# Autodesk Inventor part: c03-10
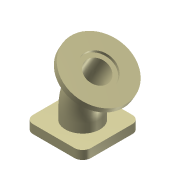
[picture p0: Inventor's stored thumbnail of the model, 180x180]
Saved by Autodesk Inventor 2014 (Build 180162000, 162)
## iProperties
Created: 2011-11
Part Number: c03-10
Material: Iron, Cast
Document SubType Name: Modeling
Designer: Thom Tremblay
Density: 7.25 g/cm^3
Mass: 1087.5 g
Surface Area: 260 cm^2
Volume: 150 cm^3
Appearance: Nylon 6
Author: Thom Tremblay
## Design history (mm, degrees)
sketch "Sketch1"
  geometry: L1 (50, -50)-(-50, -50); L2 (-50, -50)-(-50, 50); L3 (-50, 50)-(50, 50); L4 (50, 50)-(50, -50); C1 r 20 at (0, 0); C2 r 30 at (0, 0); 3 further points
  constraints: 8 end point, 2 centre point, 2 coincident, 2 midpoint, 2 parallel, 2 perpendicular, 1 horizontal, 1 horizontal alignment, 1 vertical alignment
  dimensions: "d0" = 100 distance of L2.end L3.end; "d3" = 40 diameter of C1; "d4" = 10 radial gap between concentric circles of C2 C1
extrude "Extrusion1" new body sketch "Sketch1" distance "d1" = 15; taper "d2" = 0 deg
sketch "Sketch2"
  geometry: L1 (0, 0)-(0, 30); L2 (12.794, 77.746)-(27.794, 103.727); A1 r 95.493 centre (95.493, 30) between (12.794, 77.746) and (0, 30)
  constraints: 4 end point, 2 point on circle, 2 tangent, 1 centre point, 1 vertical
  dimensions: "d5" = 30 distance of L1.start L1.end; "d7" = 50 dimension on A1; "d9" = 30 distance of L2.start L2.end; "d10" = 30 deg angle of L2 L1
sketch "Sketch3"
  geometry: L1 (12.794, 77.746)-(27.794, 103.727) reference; L2 (27.794, 103.727)-(75.425, 76.227); L3 (75.425, 76.227)-(70.425, 67.567); L4 (70.425, 67.567)-(22.794, 95.067); L5 (22.794, 95.067)-(27.794, 103.727); 2 further points
  constraints: 8 end point, 2 parallel, 2 perpendicular
  dimensions: "d11" = 110 diameter of L3 L5; "d13" = 10 distance between parallel lines of L2 L4
revolve "Revolution1" sketch "Sketch3" stored, may be unused: angle "d14" = 90 deg
sweep "Sweep1" dims "d15" = 0
sweep "Sweep2" dims "d16" = 0
sketch "Sketch4"
  geometry: C1 r 55 at (0, 0) reference; C2 r 27.5 at (0, 0); 1 further point
  constraints: 1 centre point, 1 coincident
  dimensions: "d17" = 55 diameter of C2
extrude "Extrusion2" cut sketch "Sketch4" distance "d18" = 5; taper "d19" = 0 deg
fillet "Fillet1" dims "d20" = 14
body "Solid1"
